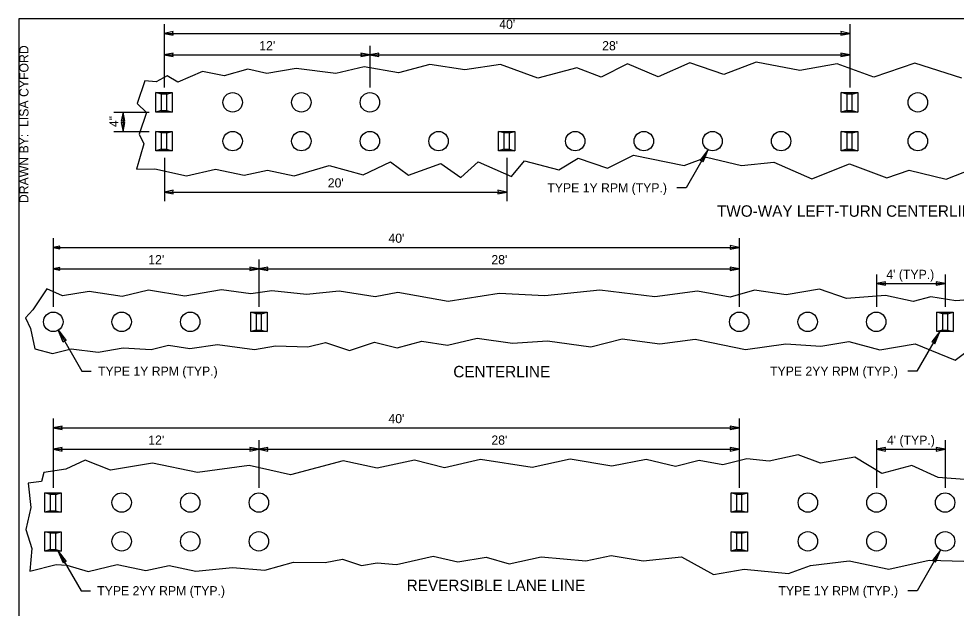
# Model space of a CAD drawing. Extents: x 99862 to 103151, y 100000 to 102076.
# Drawn here: x 99862 to 101501, y 101045 to 102076 of the extents above; entities that cross this region are included whole.
import ezdxf

# ---------------------------------------------------------------- set-up
doc = ezdxf.new("R2010")
doc.units = 0
for name, color, linetype in [('Level 1', 7, 'Continuous'), ('Level 11', 7, 'Continuous'), ('Level 15', 7, 'Continuous'), ('Level 20', 7, 'Continuous'), ('Level 50', 7, 'Continuous'), ('Level 62', 7, 'Continuous')]:
    doc.layers.add(name, color=color, linetype=linetype)

msp = doc.modelspace()

# ---------------------------------------------------------------- linework, layer by layer
at = {"layer": 'Level 1'}
msp.add_lwpolyline([(99862, 99999.5), (103151, 99999.5), (103151, 102075.5), (99862, 102075.5)], close=True, dxfattribs=at)
at = {"layer": 'Level 11'}
for p, q in [((100111.3, 101943.7), (100101.8, 101946.4)), ((100101.8, 101946.4), (100130.4, 101946.4)), ((100120.9, 101943.7), (100130.4, 101946.4)), ((101309.9, 101943.7), (101300.4, 101946.4)), ((101300.4, 101946.4), (101329, 101946.4)), ((101319.4, 101943.7), (101329, 101946.4)), ((100111.3, 101915.1), (100101.8, 101912.5)), ((100120.9, 101915.1), (100130.4, 101912.5)), ((101309.9, 101915.1), (101300.4, 101912.5)), ((101319.4, 101915.1), (101329, 101912.5)), ((100111.3, 101875.9), (100101.8, 101878.5)), ((100101.8, 101878.5), (100130.4, 101878.5)), ((100120.9, 101875.9), (100130.4, 101878.5)), ((100710.4, 101875.9), (100700.9, 101878.5)), ((100700.9, 101878.5), (100729.4, 101878.5)), ((100719.9, 101875.9), (100729.4, 101878.5)), ((101309.9, 101875.9), (101300.4, 101878.5)), ((101300.4, 101878.5), (101329, 101878.5)), ((101319.4, 101875.9), (101329, 101878.5)), ((100111.3, 101847.3), (100101.8, 101844.6)), ((100120.9, 101847.3), (100130.4, 101844.6)), ((100710.4, 101847.3), (100700.9, 101844.6)), ((100719.9, 101847.3), (100729.4, 101844.6)), ((101309.9, 101847.3), (101300.4, 101844.6)), ((101319.4, 101847.3), (101329, 101844.6)), ((100277.2, 101560), (100267.6, 101562.7)), ((100267.6, 101562.7), (100296.2, 101562.7)), ((100286.7, 101560), (100296.2, 101562.7)), ((101477.2, 101560), (101467.6, 101562.7)), ((101467.6, 101562.7), (101496.2, 101562.7)), ((101486.7, 101560), (101496.2, 101562.7)), ((100277.2, 101531.4), (100267.6, 101528.7)), ((100286.7, 101531.4), (100296.2, 101528.7)), ((101477.2, 101531.4), (101467.6, 101528.7)), ((101486.7, 101531.4), (101496.2, 101528.7)), ((99917.2, 101244.1), (99907.6, 101246.8)), ((99907.6, 101246.8), (99936.2, 101246.8)), ((99926.7, 101244.1), (99936.2, 101246.8)), ((101117.2, 101244.1), (101107.6, 101246.8)), ((101107.6, 101246.8), (101136.2, 101246.8)), ((101126.7, 101244.1), (101136.2, 101246.8)), ((99917.2, 101215.5), (99907.6, 101212.9)), ((99926.7, 101215.5), (99936.2, 101212.9)), ((101117.2, 101215.5), (101107.6, 101212.9)), ((101126.7, 101215.5), (101136.2, 101212.9)), ((99917.2, 101176.2), (99907.6, 101178.9)), ((99907.6, 101178.9), (99936.2, 101178.9)), ((99926.7, 101176.2), (99936.2, 101178.9)), ((101117.2, 101176.2), (101107.6, 101178.9)), ((101107.6, 101178.9), (101136.2, 101178.9)), ((101126.7, 101176.2), (101136.2, 101178.9)), ((99917.2, 101147.7), (99907.6, 101145)), ((99926.7, 101147.7), (99936.2, 101145)), ((101117.2, 101147.7), (101107.6, 101145)), ((101126.7, 101147.7), (101136.2, 101145))]:
    msp.add_line(p, q, dxfattribs=at)
for points in [[(100101.8, 101946.4), (100130.4, 101946.4)], [(100130.4, 101946.4), (100130.4, 101912.5), (100101.8, 101912.5), (100101.8, 101946.4)], [(101300.4, 101946.4), (101329, 101946.4)], [(101329, 101946.4), (101329, 101912.5), (101300.4, 101912.5), (101300.4, 101946.4)], [(100101.8, 101878.5), (100130.4, 101878.5)], [(100130.4, 101878.5), (100130.4, 101844.6), (100101.8, 101844.6), (100101.8, 101878.5)], [(100700.9, 101878.5), (100729.4, 101878.5)], [(100729.4, 101878.5), (100729.4, 101844.6), (100700.9, 101844.6), (100700.9, 101878.5)], [(101300.4, 101878.5), (101329, 101878.5)], [(101329, 101878.5), (101329, 101844.6), (101300.4, 101844.6), (101300.4, 101878.5)], [(100267.6, 101562.7), (100296.2, 101562.7)], [(100296.2, 101562.7), (100296.2, 101528.7), (100267.6, 101528.7), (100267.6, 101562.7)], [(101467.6, 101562.7), (101496.2, 101562.7)], [(101496.2, 101562.7), (101496.2, 101528.7), (101467.6, 101528.7), (101467.6, 101562.7)], [(99907.6, 101246.8), (99936.2, 101246.8)], [(99936.2, 101246.8), (99936.2, 101212.9), (99907.6, 101212.9), (99907.6, 101246.8)], [(101107.6, 101246.8), (101136.2, 101246.8)], [(101136.2, 101246.8), (101136.2, 101212.9), (101107.6, 101212.9), (101107.6, 101246.8)], [(99907.6, 101178.9), (99936.2, 101178.9)], [(99936.2, 101178.9), (99936.2, 101145), (99907.6, 101145), (99907.6, 101178.9)], [(101107.6, 101178.9), (101136.2, 101178.9)], [(101136.2, 101178.9), (101136.2, 101145), (101107.6, 101145), (101107.6, 101178.9)]]:
    msp.add_lwpolyline(points, dxfattribs=at)
for points in [[(100111.3, 101915.1), (100120.9, 101915.1), (100120.9, 101943.7), (100111.3, 101943.7)], [(101309.9, 101915.1), (101319.4, 101915.1), (101319.4, 101943.7), (101309.9, 101943.7)], [(100111.3, 101847.3), (100120.9, 101847.3), (100120.9, 101875.9), (100111.3, 101875.9)], [(100710.4, 101847.3), (100719.9, 101847.3), (100719.9, 101875.9), (100710.4, 101875.9)], [(101309.9, 101847.3), (101319.4, 101847.3), (101319.4, 101875.9), (101309.9, 101875.9)], [(100277.2, 101531.4), (100286.7, 101531.4), (100286.7, 101560), (100277.2, 101560)], [(101477.2, 101531.4), (101486.7, 101531.4), (101486.7, 101560), (101477.2, 101560)], [(99917.2, 101215.5), (99926.7, 101215.5), (99926.7, 101244.1), (99917.2, 101244.1)], [(101117.2, 101215.5), (101126.7, 101215.5), (101126.7, 101244.1), (101117.2, 101244.1)], [(99917.2, 101147.7), (99926.7, 101147.7), (99926.7, 101176.2), (99917.2, 101176.2)], [(101117.2, 101147.7), (101126.7, 101147.7), (101126.7, 101176.2), (101117.2, 101176.2)]]:
    msp.add_lwpolyline(points, close=True, dxfattribs=at)
for centre in [(100236.1, 101929.4), (100356.1, 101929.4), (100476.1, 101929.4), (101434.2, 101929.4), (100236.1, 101861.6), (100356.1, 101861.6), (100476.1, 101861.6), (100596.1, 101861.6), (100835.1, 101861.6), (100955.1, 101861.6), (101075.1, 101861.6), (101195.1, 101861.6), (101434.2, 101861.6), (99922.4, 101545.7), (100041.9, 101545.7), (100161.9, 101545.7), (101121.9, 101545.7), (101241.5, 101545.7), (101361.5, 101545.7), (100041.9, 101229.8), (100161.9, 101229.8), (100281.9, 101229.8), (101241.9, 101229.8), (101361.9, 101229.8), (101481.9, 101229.8), (100041.9, 101162), (100161.9, 101162), (100281.9, 101162), (101241.9, 101162), (101361.9, 101162), (101481.9, 101162)]:
    msp.add_circle(centre, 17, dxfattribs=at)
at = {"layer": 'Level 15'}
for p, q in [((100116.1, 102065.9), (100116.1, 101955.4)), ((101315.1, 102065.9), (101315.1, 101955.4)), ((100116.1, 102049.9), (101315.1, 102049.9)), ((100476.1, 102028.4), (100476.1, 101955.4)), ((100116.1, 102012.4), (100476.1, 102012.4)), ((100476.1, 102012.4), (101315.1, 102012.4)), ((100028.3, 101912.5), (100089.8, 101912.5)), ((100044.3, 101912.5), (100044.3, 101878.5)), ((100028.3, 101878.5), (100089.8, 101878.5)), ((101067.4, 101846.7), (101028.9, 101780)), ((100116.6, 101832.6), (100116.6, 101756.6)), ((100715.6, 101832.6), (100715.6, 101756.6)), ((101028.9, 101780), (101012.9, 101780)), ((100116.6, 101772.6), (100715.6, 101772.6)), ((99921.9, 101691.9), (99921.9, 101571.7)), ((101121.9, 101691.9), (101121.9, 101571.7)), ((99921.9, 101675.9), (101121.9, 101675.9)), ((100281.9, 101654.4), (100281.9, 101571.7)), ((99921.9, 101638.4), (100281.9, 101638.4)), ((100281.9, 101638.4), (101121.9, 101638.4)), ((101361.9, 101628.2), (101361.9, 101571.7)), ((101481.9, 101628.2), (101481.9, 101571.7)), ((101361.9, 101612.7), (101481.9, 101612.7)), ((99931, 101531.6), (99972.6, 101459.5)), ((101472.6, 101528.7), (101432.6, 101459.5)), ((99972.6, 101459.5), (99988.6, 101459.5)), ((101432.6, 101459.5), (101416.6, 101459.5)), ((99921.9, 101376.5), (99921.9, 101255.8)), ((101121.9, 101376.5), (101121.9, 101255.8)), ((99921.9, 101360.5), (101121.9, 101360.5)), ((100281.9, 101339), (100281.9, 101255.8)), ((101361.9, 101339), (101361.9, 101255.8)), ((101481.9, 101339), (101481.9, 101255.8)), ((99921.9, 101323), (100281.9, 101323)), ((100281.9, 101323), (101121.9, 101323)), ((101361.9, 101323), (101481.9, 101323)), ((99931.2, 101145), (99971.2, 101075.7)), ((101474.1, 101146.9), (101433, 101075.7)), ((99971.2, 101075.7), (99987.2, 101075.7)), ((101433, 101075.7), (101417, 101075.7))]:
    msp.add_line(p, q, dxfattribs=at)
for points in [[(100116.1, 102049.9), (100131.8, 102046.8), (100131.1, 102049.9), (100131.8, 102053)], [(101315.1, 102049.9), (101299.4, 102053), (101300.1, 102049.9), (101299.4, 102046.8)], [(100116.1, 102012.4), (100131.8, 102009.3), (100131.1, 102012.4), (100131.8, 102015.5)], [(100476.1, 102012.4), (100460.4, 102015.5), (100461.1, 102012.4), (100460.4, 102009.3)], [(100476.1, 102012.4), (100491.8, 102009.3), (100491.1, 102012.4), (100491.8, 102015.5)], [(101315.1, 102012.4), (101299.4, 102015.5), (101300.1, 102012.4), (101299.4, 102009.3)], [(100044.3, 101912.5), (100041.2, 101896.7), (100044.3, 101897.5), (100047.3, 101896.7)], [(100044.3, 101878.5), (100047.3, 101894.3), (100044.3, 101893.5), (100041.2, 101894.3)], [(101067.4, 101846.7), (101053.4, 101828.4), (101056.6, 101827.9), (101058.6, 101825.5)], [(100116.6, 101772.6), (100132.3, 101769.5), (100131.6, 101772.6), (100132.3, 101775.7)], [(100715.6, 101772.6), (100699.9, 101775.7), (100700.6, 101772.6), (100699.9, 101769.5)], [(99921.9, 101675.9), (99933.7, 101673.6), (99933.2, 101675.9), (99933.7, 101678.2)], [(101121.9, 101675.9), (101106.2, 101679), (101106.9, 101675.9), (101106.2, 101672.8)], [(99921.9, 101638.4), (99933.7, 101636.1), (99933.2, 101638.4), (99933.7, 101640.7)], [(100281.9, 101638.4), (100266.2, 101641.5), (100266.9, 101638.4), (100266.2, 101635.3)], [(100281.9, 101638.4), (100297.7, 101635.3), (100296.9, 101638.4), (100297.7, 101641.5)], [(101121.9, 101638.4), (101106.2, 101641.5), (101106.9, 101638.4), (101106.2, 101635.3)], [(101361.9, 101612.7), (101377.7, 101609.6), (101376.9, 101612.7), (101377.7, 101615.7)], [(101481.9, 101612.7), (101466.2, 101615.7), (101466.9, 101612.7), (101466.2, 101609.6)], [(99931, 101531.6), (99945, 101513.3), (99941.9, 101512.7), (99939.8, 101510.3)], [(101472.6, 101528.7), (101458.6, 101510.5), (101461.7, 101509.9), (101463.8, 101507.5)], [(99921.9, 101360.5), (99937.7, 101357.4), (99936.9, 101360.5), (99937.7, 101363.5)], [(101121.9, 101360.5), (101106.2, 101363.5), (101106.9, 101360.5), (101106.2, 101357.4)], [(99921.9, 101323), (99937.7, 101319.9), (99936.9, 101323), (99937.7, 101326)], [(100281.9, 101323), (100266.2, 101326), (100266.9, 101323), (100266.2, 101319.9)], [(100281.9, 101323), (100297.7, 101319.9), (100296.9, 101323), (100297.7, 101326)], [(101121.9, 101323), (101106.2, 101326), (101106.9, 101323), (101106.2, 101319.9)], [(101361.9, 101323), (101377.7, 101319.9), (101376.9, 101323), (101377.7, 101326)], [(101481.9, 101323), (101466.2, 101326), (101466.9, 101323), (101466.2, 101319.9)], [(99931.2, 101145), (99945.2, 101126.7), (99942.1, 101126.1), (99940.1, 101123.7)], [(101474.1, 101146.9), (101460.1, 101128.6), (101463.2, 101128), (101465.3, 101125.6)]]:
    msp.add_lwpolyline(points, close=True, dxfattribs=at)
at = {"layer": 'Level 50'}
for points in [[(101511.1, 101971.7), (101428.9, 101997.8), (101357.2, 101973.4), (101292.9, 101997), (101227.8, 101984.8), (101151.3, 101999.4), (101095.1, 101978.2), (101035.7, 101998.6), (100980.4, 101974.2), (100926.6, 101997), (100880.3, 101973.4), (100837.9, 101989.6), (100769.6, 101971.7), (100704.4, 101995.3), (100641.8, 101986.4), (100580.7, 101995.3), (100526.2, 101980.7), (100466, 101991.3), (100416.3, 101979.9), (100347.1, 101988.8), (100295.8, 101979.9), (100262.5, 101987.2), (100221, 101975.8), (100183.5, 101983.1), (100140.4, 101964.4), (100121.7, 101975.8), (100102.1, 101965.2), (100082.2, 101966.9), (100069.2, 101927.4), (100085.4, 101911.9), (100072.4, 101873.9), (100080.6, 101856.6), (100067.7, 101812.6), (100099.8, 101813), (100155.2, 101800.8), (100206.1, 101812.6), (100256.1, 101802), (100297.2, 101811), (100343.6, 101801.2), (100404.7, 101819.1), (100464.1, 101802.9), (100512.1, 101825.6), (100543.8, 101802), (100600, 101822.4), (100635, 101798), (100665.1, 101825.6), (100723.7, 101799.6), (100746.5, 101827.3), (100806.7, 101811.4), (100840.5, 101831.7), (100891.4, 101814.3), (100937, 101837), (101025.7, 101819.1), (101064.6, 101833.6), (101125.8, 101819.1), (101182.6, 101825), (101248.7, 101795.5), (101314.9, 101822.2), (101380.2, 101797.2), (101418.8, 101811), (101484, 101795.1), (101530, 101813)], [(101535.4, 101585.5), (101500.8, 101582.3), (101456.9, 101589.6), (101425.9, 101581.4), (101377.9, 101592), (101309.5, 101586.3), (101262.3, 101602.6), (101203.7, 101592.8), (101148.4, 101601), (101106.1, 101588.8), (101049.1, 101599.4), (100974.2, 101589.6), (100878.2, 101601), (100782.1, 101591.2), (100702.3, 101595.3), (100612.8, 101581.4), (100524.9, 101596.9), (100485, 101589.6), (100422.4, 101599.4), (100365.4, 101593.7), (100304.3, 101600.2), (100268.1, 101594.9), (100216.4, 101601.4), (100152.5, 101590.4), (100089, 101601), (100042.6, 101590), (99985.3, 101598.9), (99938.5, 101591.2), (99911.2, 101603.4), (99886.8, 101566.8), (99873.8, 101553), (99882.7, 101533.8), (99890, 101498.8), (99921.3, 101490.3), (99953.9, 101498.4), (100000.9, 101492.9), (100044.3, 101500.1), (100093.3, 101497.4), (100123.6, 101504.9), (100161.3, 101499), (100209.5, 101506.2), (100274.4, 101497.4), (100310.8, 101503.7), (100367.6, 101502.3), (100398.3, 101509.6), (100440.6, 101495.6), (100483.8, 101510.4), (100523.9, 101500.1), (100566.9, 101511.7), (100611.8, 101504.9), (100663.5, 101517), (100725.5, 101508.6), (100786.8, 101512.4), (100862.5, 101502.3), (100917.2, 101516.3), (100983, 101507.2), (101044.8, 101515.5), (101073.3, 101509.6), (101132.7, 101497.4), (101203.5, 101507.2), (101264.6, 101503.1), (101313.4, 101511.2), (101367.9, 101496.6), (101429.6, 101507.4), (101499.2, 101478.9), (101539.1, 101508.2)], [(101523.6, 101269.5), (101469.9, 101273.5), (101423.5, 101294.7), (101371, 101280.5), (101323.8, 101309.3), (101264, 101298.8), (101224.9, 101313), (101174.4, 101302), (101135.4, 101306.5), (101093, 101295.5), (101051.9, 101303.2), (101010.4, 101293.1), (100959.1, 101304.9), (100899.3, 101293.5), (100826.5, 101305.7), (100759.7, 101291.4), (100669.4, 101305.3), (100606.7, 101290.6), (100553.8, 101303.7), (100488.7, 101289.8), (100429.3, 101302.8), (100337.3, 101278.4), (100264.9, 101294.7), (100174.5, 101282.5), (100095.6, 101298.8), (100022.3, 101286.6), (99978.3, 101303.7), (99944.2, 101288.2), (99905.9, 101282.5), (99901.5, 101266.6), (99878.2, 101263.8), (99883.1, 101221.4), (99874.4, 101182.6), (99884.7, 101149.8)], [(99884.7, 101149.8), (99881.5, 101109.9), (99927.7, 101121.8), (99945.8, 101120.6), (99983.2, 101109.5), (100034.1, 101121.3), (100084.1, 101110.8), (100125.2, 101119.7), (100171.6, 101109.9), (100235.6, 101116.4), (100292.1, 101111.6), (100342.2, 101125.4), (100397.7, 101124.8), (100428, 101131.1), (100461.2, 101119.9), (100488.7, 101124.6), (100522.4, 101121.3), (100586.4, 101136), (100629.7, 101126.4), (100679.2, 101134.4), (100719.4, 101123), (100775.6, 101135.2), (100853.7, 101127.9), (100897.7, 101137.2), (100953.8, 101127.9), (101021, 101134.8), (101076.7, 101104.3), (101130.4, 101113.2), (101208.2, 101105.9), (101246.8, 101119.7), (101314.2, 101128), (101383.6, 101113.2), (101454.2, 101128.9), (101514.5, 101127.2)]]:
    msp.add_lwpolyline(points, dxfattribs=at)

# ---------------------------------------------------------------- texts
at = {"layer": 'Level 20'}
for s, rotation, p in [("40'", 0, (100702.2, 102057.9)), ("12'", 0, (100282.6, 102020.4)), ("28'", 0, (100882.2, 102020.4)), ('4"', 90, (100036.3, 101886.1)), ("20'", 0, (100402.4, 101780.6)), ("40'", 0, (100508.5, 101683.9)), ("12'", 0, (100088.5, 101646.4)), ("28'", 0, (100688.5, 101646.4)), ("4' (TYP.)", 0, (101379.1, 101620.7)), ("40'", 0, (100508.5, 101368.5)), ("12'", 0, (100088.5, 101331)), ("28'", 0, (100688.5, 101331)), ("4' (TYP.)", 0, (101380.2, 101330.9))]:
    msp.add_text(s, height=16, rotation=rotation, dxfattribs=at).set_placement(p)
for s, height, p in [('TYPE 1Y RPM (TYP.)', 16, (100786.3, 101772)), ('TWO-WAY LEFT-TURN CENTERLINE', 20, (101083, 101729.4)), ('TYPE 1Y RPM (TYP.)', 16, (100000.6, 101451.5)), ('CENTERLINE', 20, (100621.9, 101448.7)), ('TYPE 2YY RPM (TYP.)', 16, (101175.8, 101451.5)), ('TYPE 2YY RPM (TYP.)', 16, (99999.2, 101067.7)), ('REVERSIBLE LANE LINE', 20, (100540.4, 101075)), ('TYPE 1Y RPM (TYP.)', 16, (101190.4, 101067.7))]:
    msp.add_text(s, height=height, dxfattribs=at).set_placement(p)
at = {"layer": 'Level 62'}
msp.add_text('DRAWN BY:  LISA CYFORD', height=16, rotation=90, dxfattribs=at).set_placement((99879, 101753.3))

doc.saveas('drawing.dxf')
